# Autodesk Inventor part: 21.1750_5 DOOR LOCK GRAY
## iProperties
Created: 2007-03
Part Number: 21.1750_5 DOOR LOCK GRAY
Document SubType Name: Modeling
Designer: Andy Moles
Material: ABS Plastic
Mass: 53.493 g
Surface Area: 156.987 cm^2
Volume: 50.4651 cm^3
Density: 1.06 g/cm^3
Author: Andy Moles
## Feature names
1. Base1
